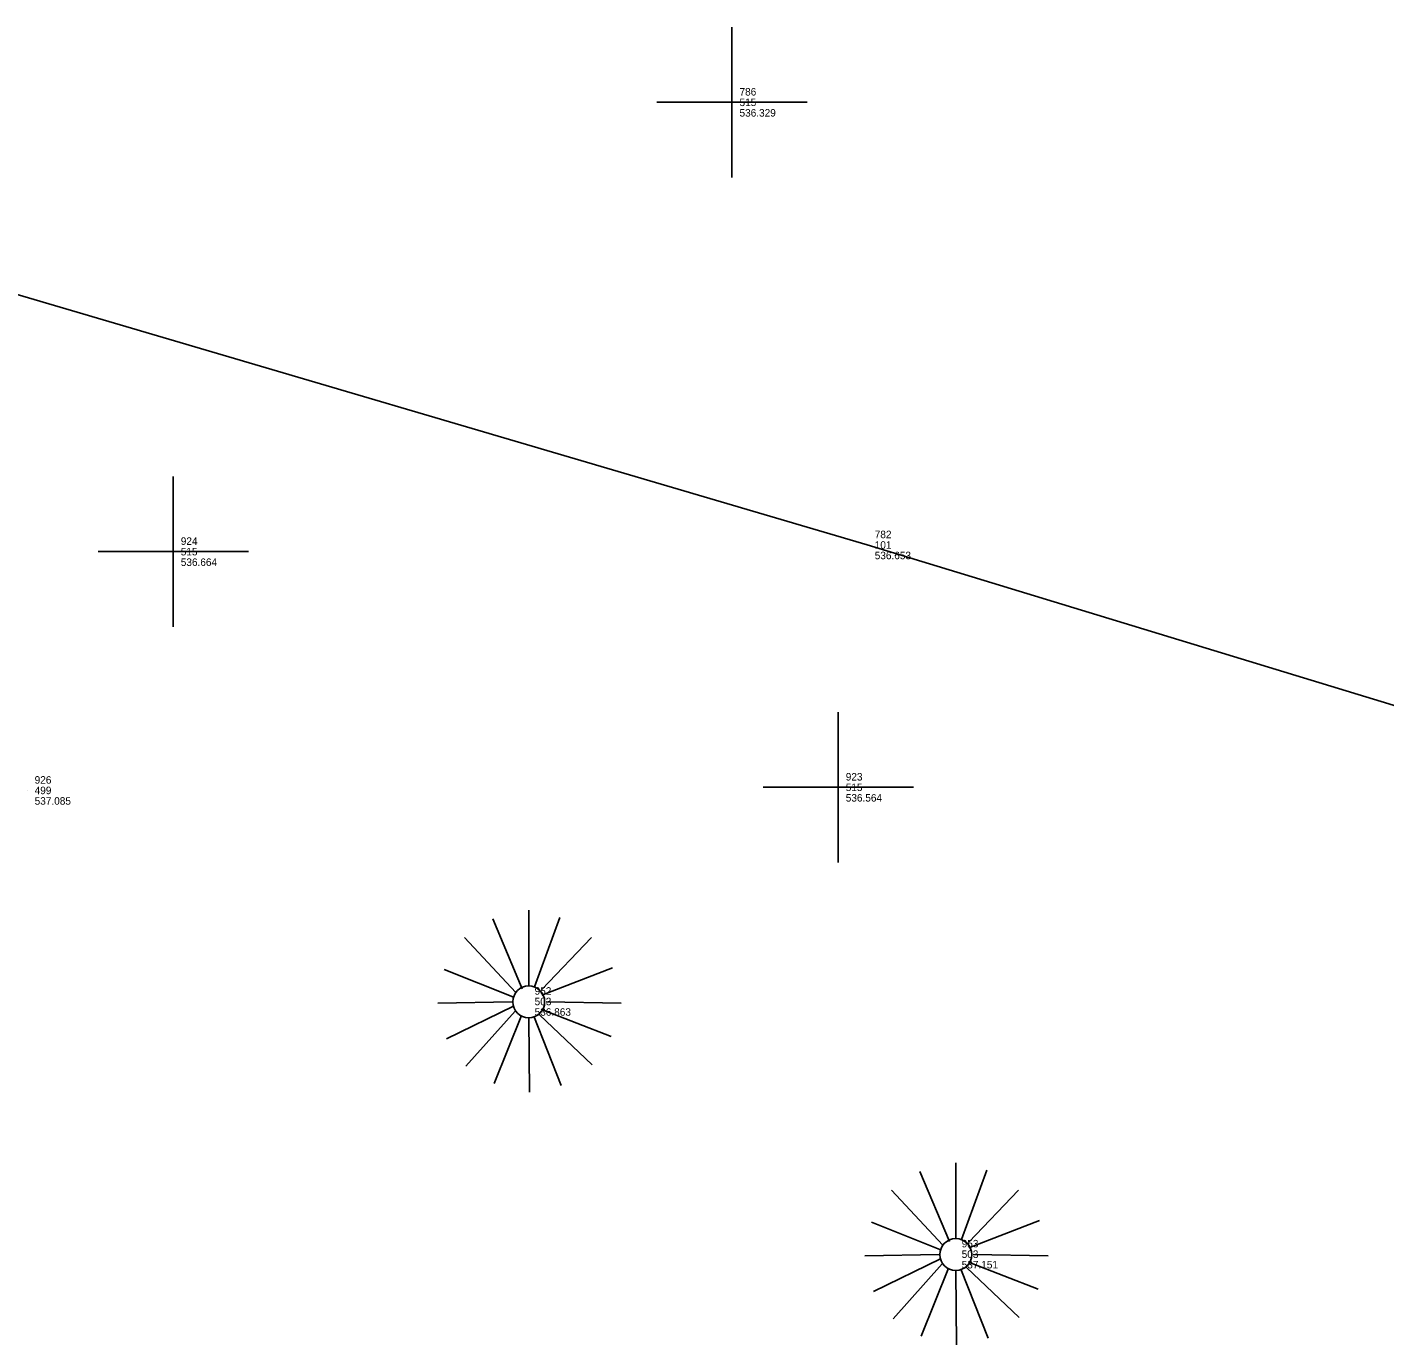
# Model space of a CAD drawing. Extents: x 5447 to 709667, y 4528 to 375505.
# Drawn here: x 706723.86 to 706769.05, y 374867.32 to 374911.17 of the extents above; entities that cross this region are included whole.
import ezdxf

# ---------------------------------------------------------------- set-up
doc = ezdxf.new("R2010")
doc.units = 0
for name, color, linetype in [('SV_NODES_ACTIVE_POINT', 7, 'Continuous'), ('SV_NODES_DESCRIPTION', 7, 'Continuous'), ('SV_NODES_ELEVATION', 7, 'Continuous'), ('SV_NODES_PT_NUMBER', 7, 'Continuous'), ('SV_ROAD_BITRD', 7, 'Continuous'), ('SV_SURF_SPOT', 7, 'Continuous'), ('SV_TREE_TREEVEG', 7, 'Continuous')]:
    doc.layers.add(name, color=color, linetype=linetype)

msp = doc.modelspace()

# ---------------------------------------------------------------- linework, layer by layer
at = {"layer": 'SV_NODES_ACTIVE_POINT'}
for p, q in [((706751.824, 374893.938), (706751.824, 374893.938)), ((706723.86, 374885.77), (706723.86, 374885.77))]:
    msp.add_line(p, q, dxfattribs=at)
at = {"layer": 'SV_ROAD_BITRD'}
msp.add_lwpolyline([(706691.73, 374902.41), (706720.085, 374903.286), (706751.824, 374893.938), (706781.127, 374885.008), (706784.789, 374896.447)], dxfattribs=at)
at = {"layer": 'SV_SURF_SPOT'}
for p, q in [((706747.323, 374906.166), (706747.323, 374911.168)), ((706744.822, 374908.667), (706749.824, 374908.667)), ((706747.323, 374908.667), (706747.323, 374908.667)), ((706728.724, 374891.214), (706728.724, 374896.216)), ((706726.223, 374893.715), (706731.225, 374893.715)), ((706728.724, 374893.715), (706728.724, 374893.715)), ((706750.86, 374883.373), (706750.86, 374888.375)), ((706748.359, 374885.874), (706753.361, 374885.874)), ((706750.86, 374885.874), (706750.86, 374885.874))]:
    msp.add_line(p, q, dxfattribs=at)
at = {"layer": 'SV_TREE_TREEVEG'}
for p, q in [((706740.557, 374879.264), (706740.557, 374881.786)), ((706741.59, 374881.544), (706740.749, 374879.238)), ((706739.357, 374881.497), (706740.342, 374879.166)), ((706738.418, 374880.873), (706740.125, 374879.046)), ((706740.991, 374879.144), (706742.648, 374880.873)), ((706740.031, 374878.901), (706737.747, 374879.815)), ((706740.991, 374878.952), (706743.344, 374879.862)), ((706740.005, 374878.734), (706737.53, 374878.687)), ((706740.053, 374878.59), (706737.82, 374877.509)), ((706740.1, 374878.423), (706738.468, 374876.596)), ((706741.013, 374878.47), (706743.297, 374877.582)), ((706741.133, 374878.734), (706743.631, 374878.687)), ((706740.317, 374878.278), (706739.404, 374876.019)), ((706740.557, 374878.183), (706740.582, 374875.73)), ((706740.723, 374878.253), (706741.637, 374875.947)), ((706740.916, 374878.303), (706742.67, 374876.643)), ((706753.573, 374873.089), (706754.558, 374870.758)), ((706754.773, 374870.856), (706754.773, 374873.378)), ((706755.806, 374873.136), (706754.965, 374870.83)), ((706752.634, 374872.465), (706754.341, 374870.638)), ((706755.207, 374870.736), (706756.864, 374872.465)), ((706754.247, 374870.493), (706751.963, 374871.407)), ((706755.207, 374870.544), (706757.56, 374871.454)), ((706754.221, 374870.326), (706751.746, 374870.279)), ((706755.349, 374870.326), (706757.847, 374870.279)), ((706754.269, 374870.182), (706752.036, 374869.101)), ((706754.316, 374870.015), (706752.684, 374868.188)), ((706754.533, 374869.87), (706753.62, 374867.611)), ((706754.773, 374869.775), (706754.798, 374867.322)), ((706754.939, 374869.845), (706755.853, 374867.539)), ((706755.132, 374869.895), (706756.886, 374868.235)), ((706755.229, 374870.062), (706757.513, 374869.174))]:
    msp.add_line(p, q, dxfattribs=at)
for centre in [(706740.557, 374878.734), (706754.773, 374870.326)]:
    msp.add_circle(centre, 0.53, dxfattribs=at)

# ---------------------------------------------------------------- texts
at = {"layer": 'SV_NODES_DESCRIPTION'}
for s, p in [('515', (706747.573, 374908.542)), ('515', (706728.974, 374893.59)), ('101', (706752.074, 374893.813)), ('499', (706724.11, 374885.645)), ('515', (706751.11, 374885.749)), ('503', (706740.753, 374878.622)), ('503', (706754.969, 374870.214))]:
    msp.add_text(s, height=0.25, dxfattribs=at).set_placement(p)
at = {"layer": 'SV_NODES_ELEVATION'}
for s, p in [('536.329', (706747.573, 374908.192)), ('536.664', (706728.974, 374893.24)), ('536.653', (706752.074, 374893.463)), ('536.564', (706751.11, 374885.399)), ('537.085', (706724.11, 374885.295)), ('536.863', (706740.753, 374878.272)), ('537.151', (706754.969, 374869.864))]:
    msp.add_text(s, height=0.25, dxfattribs=at).set_placement(p)
at = {"layer": 'SV_NODES_PT_NUMBER'}
for s, p in [('786', (706747.573, 374908.892)), ('924', (706728.974, 374893.94)), ('782', (706752.074, 374894.163)), ('926', (706724.11, 374885.995)), ('923', (706751.11, 374886.099)), ('952', (706740.753, 374878.972)), ('953', (706754.969, 374870.564))]:
    msp.add_text(s, height=0.25, dxfattribs=at).set_placement(p)

doc.saveas('drawing.dxf')
